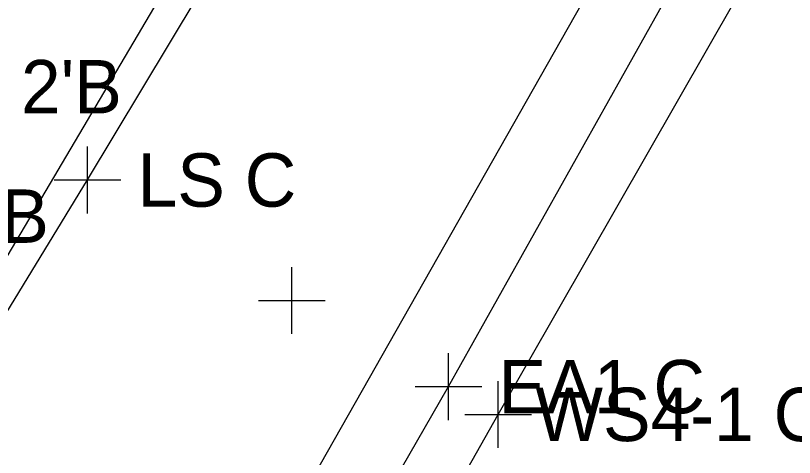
# Model space of a CAD drawing. Extents: x 1363693 to 1365209, y 422201 to 424153.
# Drawn here: x 1364089.1 to 1364112.45, y 422799.79 to 422813.03 of the extents above; entities that cross this region are included whole.
import ezdxf

# ---------------------------------------------------------------- set-up
doc = ezdxf.new("R2010")
doc.units = 0
for name, color, linetype in [('OWNERS', 7, 'Continuous'), ('PM_X_Channelizing_Line', 7, 'Continuous'), ('PM_X_Edge_Line', 7, 'Continuous'), ('SV_X_Original_Ground', 7, 'Continuous'), ('SV_X_Random_Point', 7, 'Continuous'), ('SV_X_Shot_Marker', 7, 'Continuous'), ('UT_X_FO', 7, 'Continuous'), ('UT_X_Gas', 7, 'Continuous'), ('VG_X_Flower_Bed', 7, 'Continuous'), ('VG_X_Text', 7, 'Continuous')]:
    doc.layers.add(name, color=color, linetype=linetype)

msp = doc.modelspace()

# ---------------------------------------------------------------- linework, layer by layer
at = {"layer": 'OWNERS'}
msp.add_lwpolyline([(1364089.632, 422780.271), (1364102.08, 422801.911), (1364114.271, 422823.678), (1364126.868, 422845.272), (1364138.192, 422867.568), (1364150.546, 422889.234), (1364150.546, 422889.234), (1364162.879, 422910.978), (1364162.879, 422910.978), (1364170.332, 422924.545), (1364170.332, 422924.545), (1364173.925, 422931.803), (1364173.925, 422931.803), (1364182.923, 422951.414), (1364182.923, 422951.414), (1364183.888, 422953.606), (1364183.888, 422953.606), (1364188.472, 422964.837), (1364188.472, 422964.837), (1364192.543, 422975.639), (1364192.543, 422975.639), (1364193.28, 422977.776), (1364193.28, 422977.776), (1364200.007, 422998.363)], dxfattribs=at)
at = {"layer": 'PM_X_Channelizing_Line'}
for p, q in [((1364103.568, 422801.079), (1364115.929, 422822.695)), ((1364091.221, 422779.339), (1364103.568, 422801.079))]:
    msp.add_line(p, q, dxfattribs=at)
at = {"layer": 'PM_X_Edge_Line'}
for p, q in [((1364103.568, 422801.079), (1364115.929, 422822.695)), ((1364091.221, 422779.339), (1364103.568, 422801.079))]:
    msp.add_line(p, q, dxfattribs=at)
at = {"layer": 'SV_X_Original_Ground'}
for p, q in [((1364097.379, 422803.492), (1364097.379, 422805.492)), ((1364096.379, 422804.492), (1364098.379, 422804.492)), ((1364103.568, 422800.079), (1364103.568, 422802.079)), ((1364102.568, 422801.079), (1364104.568, 422801.079))]:
    msp.add_line(p, q, dxfattribs=at)
at = {"layer": 'SV_X_Random_Point'}
for p, q in [((1364091.259, 422807.103), (1364091.259, 422809.103)), ((1364090.259, 422808.103), (1364092.259, 422808.103))]:
    msp.add_line(p, q, dxfattribs=at)
at = {"layer": 'SV_X_Shot_Marker'}
for p, q in [((1364102.08, 422800.911), (1364102.08, 422802.911)), ((1364101.08, 422801.911), (1364103.08, 422801.911))]:
    msp.add_line(p, q, dxfattribs=at)
at = {"layer": 'UT_X_FO'}
msp.add_lwpolyline([(1364198.41, 423083.145), (1364202.916, 423079.215), (1364206.614, 423072.625), (1364206.927, 423065.384), (1364205.607, 423052.889), (1364202.652, 423033.176), (1364193.585, 423006.537), (1364182.955, 422981.103), (1364130.325, 422876.058), (1364040.63, 422724.214)], dxfattribs=at)
at = {"layer": 'UT_X_Gas'}
msp.add_lwpolyline([(1364207.557, 423089.372), (1364211.518, 423072.856), (1364208.943, 423046.381), (1364201.649, 423012.485), (1364191.712, 422981.617), (1364181.14, 422953.292), (1364166.466, 422921.961), (1364127.708, 422851.525), (1364051.86, 422717.903)], dxfattribs=at)
at = {"layer": 'VG_X_Flower_Bed'}
for p, q in [((1364091.259, 422808.103), (1364104.088, 422829.493)), ((1364078.24, 422786.815), (1364091.259, 422808.103))]:
    msp.add_line(p, q, dxfattribs=at)

# ---------------------------------------------------------------- texts
at = {"layer": 'SV_X_Original_Ground'}
msp.add_text('WS4-1 C', height=1.6, dxfattribs=at).set_placement((1364104.687, 422800.279))
at = {"layer": 'SV_X_Random_Point'}
msp.add_text('LS C', height=1.6, dxfattribs=at).set_placement((1364092.759, 422807.303))
at = {"layer": 'SV_X_Shot_Marker'}
msp.add_text('EA1 C', height=1.6, dxfattribs=at).set_placement((1364103.58, 422801.111))
at = {"layer": 'VG_X_Text'}
for p in [(1364089.265, 422810.098), (1364087.078, 422806.22)]:
    msp.add_text("2'B", height=1.6, dxfattribs=at).set_placement(p)

doc.saveas('drawing.dxf')
